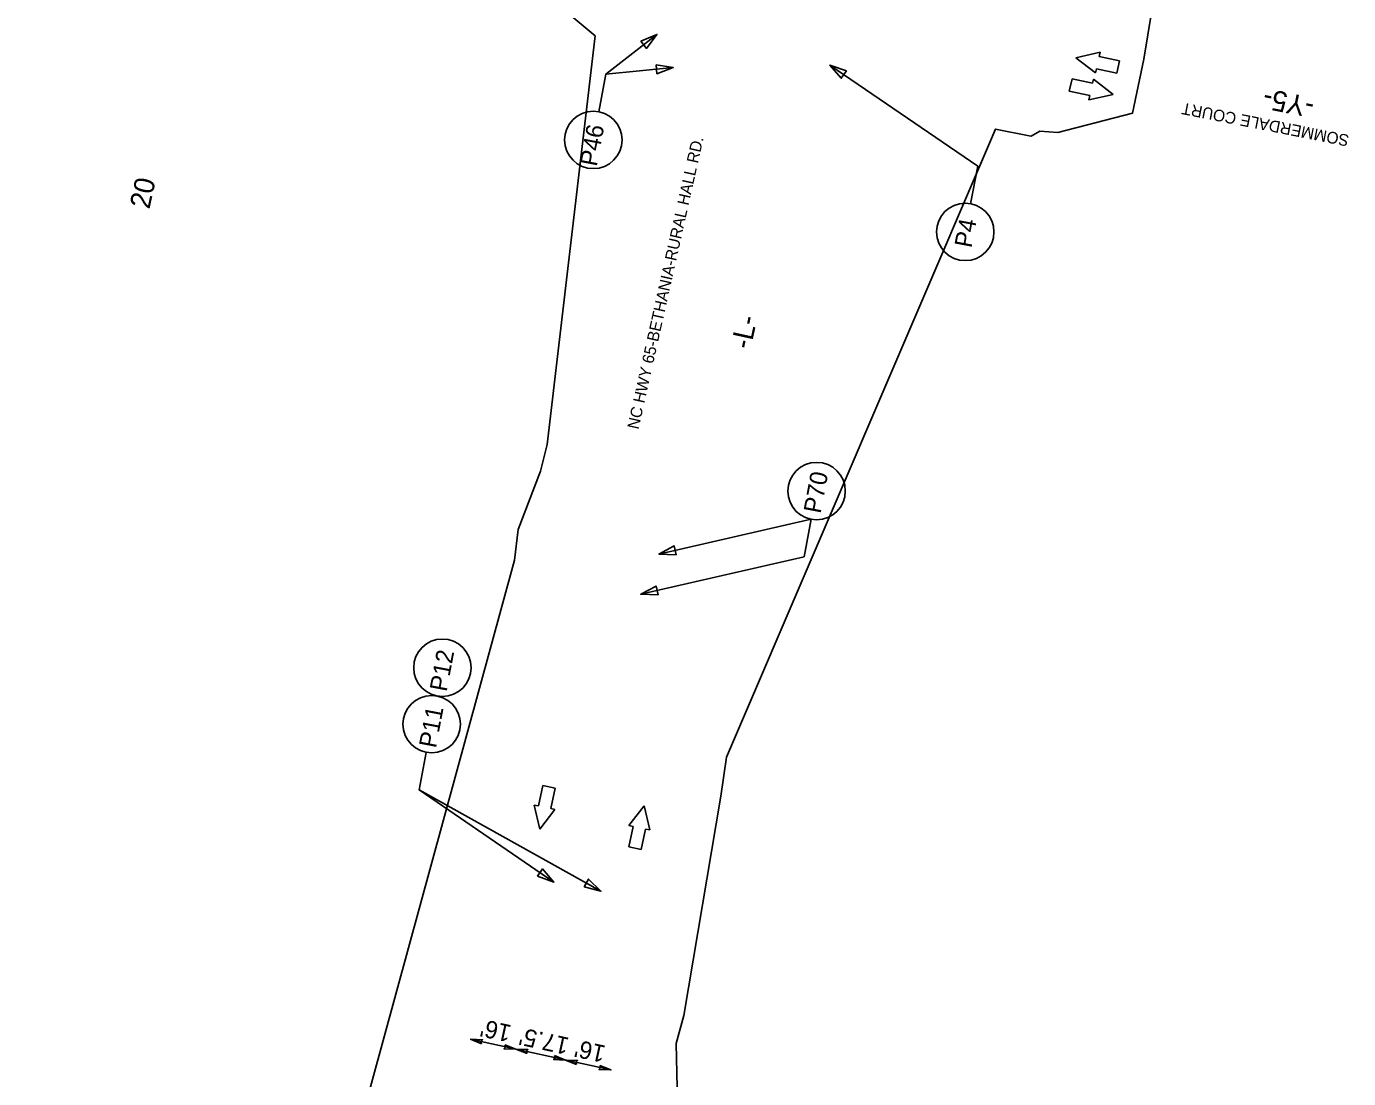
# Model space of a CAD drawing. Extents: x 1615680 to 1619687, y 899305 to 902270.
# Drawn here: x 1616168.2 to 1616623.7, y 900338.4 to 900701 of the extents above; entities that cross this region are included whole.
import ezdxf

# ---------------------------------------------------------------- set-up
doc = ezdxf.new("R2010")
doc.units = 0
for name, color, linetype in [('Default', 7, 'Continuous'), ('DEV DRUM PLAN VIEW CELL', 7, 'Continuous'), ('Prop Conc 2ft 6in Curb and Gutter', 7, 'Continuous'), ('Prop Conc 5in Monolithic Keyed In Island', 7, 'Continuous'), ('Prop Conc Valley Gutter', 7, 'Continuous')]:
    doc.layers.add(name, color=color, linetype=linetype)

msp = doc.modelspace()

# ---------------------------------------------------------------- linework, layer by layer
at = {"layer": 'Default'}
for p, q in [((1616367.82, 900684.55), (1616385.44, 900698.22)), ((1616438.6, 900531.14), (1616386.09, 900519.11)), ((1616303.52, 900437.85), (1616366.13, 900402.95))]:
    msp.add_line(p, q, dxfattribs=at)
for points in [[(1616379.91, 900695.89), (1616385.44, 900698.22), (1616381.82, 900693.44)], [(1616385.13, 900687.78), (1616391.05, 900686.79), (1616385.43, 900684.69)], [(1616450.7, 900685.69), (1616445.04, 900687.68), (1616448.95, 900683.12)], [(1616392.09, 900518.9), (1616386.09, 900519.11), (1616391.4, 900521.92)], [(1616385.84, 900505.08), (1616379.85, 900505.3), (1616385.15, 900508.11)], [(1616344.26, 900408.07), (1616349.92, 900406.08), (1616346.02, 900410.63)], [(1616360.31, 900404.41), (1616366.13, 900402.95), (1616361.82, 900407.13)], [(1616325.04, 900350.35), (1616321.23, 900351.9), (1616325.36, 900351.73), (1616324.7, 900351.14)], [(1616333.05, 900350.03), (1616336.86, 900348.49), (1616332.73, 900348.65), (1616333.39, 900349.25)], [(1616340.67, 900346.95), (1616336.86, 900348.49), (1616340.99, 900348.33), (1616340.34, 900347.73)], [(1616350.15, 900346.31), (1616353.96, 900344.76), (1616349.83, 900344.93), (1616350.49, 900345.52)], [(1616357.77, 900343.22), (1616353.96, 900344.76), (1616358.1, 900344.6), (1616357.44, 900344.01)], [(1616365.79, 900342.9), (1616369.59, 900341.36), (1616365.46, 900341.52), (1616366.12, 900342.12)]]:
    msp.add_lwpolyline(points, close=True, dxfattribs=at)
for points in [[(1616365.36, 900671.6), (1616367.82, 900684.55), (1616391.05, 900686.79)], [(1616493.49, 900639.88), (1616495.95, 900652.82), (1616445.04, 900687.68)], [(1616438.6, 900531.14), (1616436.14, 900518.2), (1616379.85, 900505.3)], [(1616305.98, 900450.79), (1616303.52, 900437.85), (1616349.92, 900406.08)]]:
    msp.add_lwpolyline(points, dxfattribs=at)
for centre in [(1616363.52, 900661.88), (1616491.64, 900630.16), (1616440.44, 900540.86), (1616311.52, 900479.95), (1616307.83, 900460.51)]:
    msp.add_circle(centre, 9.89, dxfattribs=at)
at = {"layer": 'DEV DRUM PLAN VIEW CELL'}
msp.add_line((1616369.59, 900341.36), (1616321.23, 900351.9), dxfattribs=at)
at = {"layer": 'Prop Conc 5in Monolithic Keyed In Island'}
for p, q in [((1616538.07, 900692.11), (1616529.71, 900690.22)), ((1616529.71, 900690.22), (1616538.07, 900692.11)), ((1616529.71, 900690.22), (1616536.49, 900684.98)), ((1616536.49, 900684.98), (1616529.71, 900690.22)), ((1616537.75, 900690.67), (1616538.07, 900692.11)), ((1616538.07, 900692.11), (1616537.75, 900690.67)), ((1616544.78, 900689.11), (1616537.75, 900690.67)), ((1616537.75, 900690.67), (1616544.78, 900689.11)), ((1616543.84, 900684.87), (1616544.78, 900689.11)), ((1616544.78, 900689.11), (1616543.84, 900684.87)), ((1616536.49, 900684.98), (1616536.81, 900686.42)), ((1616536.81, 900686.42), (1616536.49, 900684.98)), ((1616536.81, 900686.42), (1616543.84, 900684.87)), ((1616543.84, 900684.87), (1616536.81, 900686.42)), ((1616528.44, 900682.95), (1616527.5, 900678.7)), ((1616527.5, 900678.7), (1616528.44, 900682.95)), ((1616527.5, 900678.7), (1616534.53, 900677.14)), ((1616534.53, 900677.14), (1616527.5, 900678.7)), ((1616535.47, 900681.39), (1616528.44, 900682.95)), ((1616528.44, 900682.95), (1616535.47, 900681.39)), ((1616535.79, 900682.83), (1616535.47, 900681.39)), ((1616535.47, 900681.39), (1616535.79, 900682.83)), ((1616542.57, 900677.59), (1616535.79, 900682.83)), ((1616535.79, 900682.83), (1616542.57, 900677.59)), ((1616534.21, 900675.7), (1616542.57, 900677.59)), ((1616542.57, 900677.59), (1616534.21, 900675.7)), ((1616534.53, 900677.14), (1616534.21, 900675.7)), ((1616534.21, 900675.7), (1616534.53, 900677.14)), ((1616346.06, 900439.37), (1616344.57, 900432.33)), ((1616350.31, 900438.47), (1616346.06, 900439.37)), ((1616348.82, 900431.43), (1616350.31, 900438.47)), ((1616344.57, 900432.33), (1616343.12, 900432.63)), ((1616343.12, 900432.63), (1616345.09, 900424.29)), ((1616345.09, 900424.29), (1616350.27, 900431.12)), ((1616350.27, 900431.12), (1616348.82, 900431.43)), ((1616381.03, 900432.39), (1616375.8, 900425.61)), ((1616382.93, 900424.04), (1616381.03, 900432.39)), ((1616377.24, 900425.29), (1616375.69, 900418.26)), ((1616375.8, 900425.61), (1616377.24, 900425.29)), ((1616379.94, 900417.32), (1616381.49, 900424.35)), ((1616381.49, 900424.35), (1616382.93, 900424.04)), ((1616375.69, 900418.26), (1616379.94, 900417.32))]:
    msp.add_line(p, q, dxfattribs=at)
at = {"layer": 'Prop Conc Valley Gutter'}
for points in [[(1616364.12, 900697.77), (1616346.17, 900712.92), (1616320.68, 900718.26), (1616317.92, 900716.06), (1616318.38, 900718.79), (1616321.17, 900737.64), (1616321.64, 900740.44), (1616360.99, 900738.34), (1616378.95, 900738.53), (1616380.95, 900738.45), (1616444.67, 901002.24), (1616598.93, 900968.63), (1616553.12, 900689.68), (1616549.22, 900671.08), (1616523.49, 900664.4), (1616517.29, 900664.94), (1616514.38, 900663.18), (1616513.71, 900663.29), (1616502.01, 900665.64), (1616409.34, 900449.1), (1616407.45, 900435.71), (1616394.68, 900360.06), (1616392.05, 900350.44), (1616393.93, 900269.36)], [(1616273.84, 899841.42), (1616273.25, 899812.18), (1616273.25, 899811.36), (1616264.99, 899807.36), (1616258.95, 899802.9), (1616253.13, 899795.75), (1616247.48, 899786.63), (1616244, 899777.92), (1616242.54, 899778.39), (1616221.34, 899877.87), (1616220.94, 899877.94), (1616226.27, 899953.84), (1616231.37, 899979.34), (1616235.41, 899998.49), (1616168.21, 900084.42), (1616170.51, 900091.83), (1616174.76, 900111.37), (1616176.76, 900111.01), (1616234.19, 900143.08), (1616336.31, 900517.08), (1616337.63, 900527.64), (1616345.35, 900547.71), (1616347.66, 900556.85), (1616364.12, 900697.77)]]:
    msp.add_lwpolyline(points, dxfattribs=at)

# ---------------------------------------------------------------- texts
at = {"layer": 'Default'}
for s, height, rotation, p in [('SOMMERDALE COURT', 4, 168.9309, (1616624.12, 900663.52)), ('P46', 6, 79.2494, (1616364.65, 900652.51)), ('NC HWY 65-BETHANIA-RURAL HALL RD.', 4, 77.4143, (1616379.06, 900561.92)), ('P4', 6, 79.2493, (1616493.76, 900624.44)), ('P70', 6, 79.2493, (1616441.78, 900532.89)), ('P12', 6, 79.2493, (1616312.96, 900471.47)), ('P11', 6, 79.2493, (1616309.27, 900452.03)), ("16'", 6, 167.6891, (1616335.61, 900356.66)), ("17.5'", 6, 167.6891, (1616355.52, 900352.32)), ("16'", 6, 167.6891, (1616368.09, 900349.59))]:
    msp.add_text(s, height=height, rotation=rotation, dxfattribs=at).set_placement(p)
at = {"layer": 'Prop Conc 2ft 6in Curb and Gutter'}
for s, rotation, p in [('-Y5-', 168.742, (1616612.31, 900676.27)), ('20', 77.7098, (1616210.56, 900637.8)), ('-L-', 77.7098, (1616417.64, 900589.43))]:
    msp.add_text(s, height=7, rotation=rotation, dxfattribs=at).set_placement(p)

doc.saveas('drawing.dxf')
